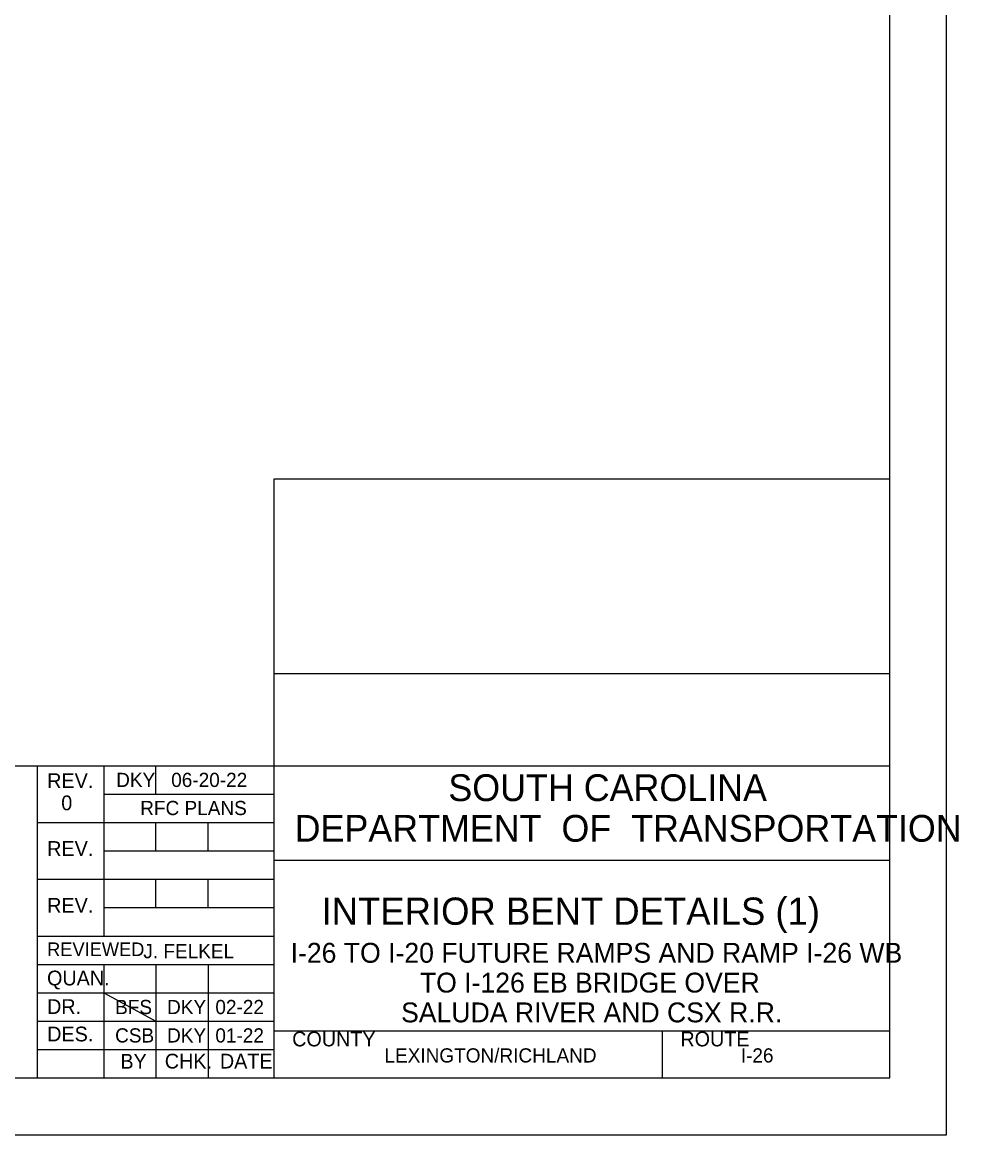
# Model space of a CAD drawing. Extents: x -133.1 to -97, y -1.7 to 20.3.
# Drawn here: x -105.28 to -97.03, y -1.69 to 8.11 of the extents above; entities that cross this region are included whole.
import ezdxf

# ---------------------------------------------------------------- set-up
doc = ezdxf.new("R2010")
doc.units = 0
for name, color, linetype in [('BR_BORDER LINES', 7, 'Continuous'), ('BR_TEXT', 7, 'Continuous'), ('Level 31', 7, 'Continuous')]:
    doc.layers.add(name, color=color, linetype=linetype)

msp = doc.modelspace()

# ---------------------------------------------------------------- linework, layer by layer
at = {"layer": 'BR_BORDER LINES'}
for p, q in [((-97.6416, -1.191), (-97.6416, 19.8089)), ((-103.0585, -1.191), (-103.0585, 4.0855)), ((-103.0585, 4.0855), (-97.6416, 4.0855)), ((-103.0583, 2.3708), (-97.6416, 2.3708)), ((-110.5071, 1.5591), (-105.1419, 1.5591)), ((-105.1419, -1.191), (-105.1419, 1.5591)), ((-105.1419, 1.5591), (-97.6416, 1.5591)), ((-104.5585, 1.5591), (-104.5585, 0.059)), ((-104.1002, 1.3091), (-104.1002, 1.5591)), ((-104.5585, 1.3091), (-103.0585, 1.3091)), ((-105.1419, 1.0591), (-103.0585, 1.0591)), ((-104.1002, 0.809), (-104.1002, 1.0591)), ((-103.6418, 0.809), (-103.6418, 1.0591)), ((-104.5585, 0.809), (-103.0585, 0.809)), ((-103.0585, 0.7257), (-103.0585, 0.7257)), ((-103.0585, 0.7257), (-97.6414, 0.7257)), ((-105.1419, 0.559), (-103.0585, 0.559)), ((-104.1002, 0.309), (-104.1002, 0.559)), ((-103.6418, 0.309), (-103.6418, 0.559)), ((-104.5585, 0.309), (-103.0585, 0.309)), ((-105.1419, 0.059), (-103.0585, 0.059)), ((-105.1419, -0.191), (-103.0585, -0.191)), ((-104.5585, -0.191), (-104.5585, -1.191)), ((-104.1002, -0.191), (-104.1002, -1.191)), ((-103.6418, -0.191), (-103.6418, -1.191)), ((-105.1419, -0.441), (-103.0585, -0.441)), ((-105.1419, -0.691), (-103.0585, -0.691)), ((-103.0585, -0.7744), (-97.6416, -0.7744)), ((-102.9609, -0.7744), (-97.6416, -0.7744)), ((-99.6417, -1.191), (-99.6417, -0.7744)), ((-105.1419, -0.941), (-103.0585, -0.941)), ((-131.3076, -1.191), (-97.6416, -1.191))]:
    msp.add_line(p, q, dxfattribs=at)
at = {"layer": 'Level 31'}
for p, q in [((-100.3498, 0.2855), (-100.3498, 0.2855)), ((-104.5585, -0.441), (-104.1002, -0.691))]:
    msp.add_line(p, q, dxfattribs=at)
msp.add_lwpolyline([(-133.1409, -1.691), (-97.141, -1.691), (-97.141, 20.309), (-133.1409, 20.309)], close=True, dxfattribs=at)

# ---------------------------------------------------------------- texts
at = {"layer": 'BR_TEXT'}
for s, height, p in [('REV.', 0.13001, (-105.0572, 1.362)), ('DKY', 0.12499, (-104.4502, 1.3715)), ('06-20-22', 0.12499, (-103.9658, 1.3715)), ('SOUTH CAROLINA', 0.23587, (-101.5266, 1.2475)), ('0', 0.13, (-104.9333, 1.167)), ('RFC PLANS', 0.12499, (-104.2386, 1.124)), ('DEPARTMENT  OF  TRANSPORTATION', 0.23587, (-102.8793, 0.8897)), ('REV.', 0.13001, (-105.0572, 0.7645)), ('REV.', 0.13001, (-105.0572, 0.2644)), ('INTERIOR BENT DETAILS (1)', 0.24, (-102.6425, 0.158)), ('REVIEWED', 0.12, (-105.0579, -0.1175)), ('I-26 TO I-20 FUTURE RAMPS AND RAMP I-26 WB', 0.175, (-102.915, -0.1761)), ('J. FELKEL', 0.125, (-104.2114, -0.1366)), ('QUAN.', 0.13001, (-105.0585, -0.3758)), ('TO I-126 EB BRIDGE OVER', 0.175, (-101.777, -0.4386)), ('DR.', 0.13001, (-105.0583, -0.6274)), ('BFS', 0.12499, (-104.4595, -0.6286)), ('DKY', 0.12499, (-104.002, -0.6286)), ('02-22', 0.12499, (-103.5772, -0.6286)), ('SALUDA RIVER AND CSX R.R.', 0.175, (-101.9427, -0.7011)), ('DES.', 0.13001, (-105.0572, -0.8687)), ('CSB', 0.12499, (-104.4595, -0.8786)), ('DKY', 0.12499, (-104.002, -0.8786)), ('01-22', 0.12499, (-103.5772, -0.8786)), ('COUNTY', 0.13001, (-102.9012, -0.9127)), ('ROUTE', 0.13001, (-99.4844, -0.9127)), ('BY', 0.13001, (-104.4132, -1.109)), ('CHK.', 0.13001, (-104.0224, -1.1077)), ('DATE', 0.13001, (-103.5372, -1.1076)), ('LEXINGTON/RICHLAND', 0.124995, (-102.089, -1.0548)), ('I-26', 0.12499, (-98.953, -1.0548))]:
    msp.add_text(s, height=height, dxfattribs=at).set_placement(p)

doc.saveas('drawing.dxf')
